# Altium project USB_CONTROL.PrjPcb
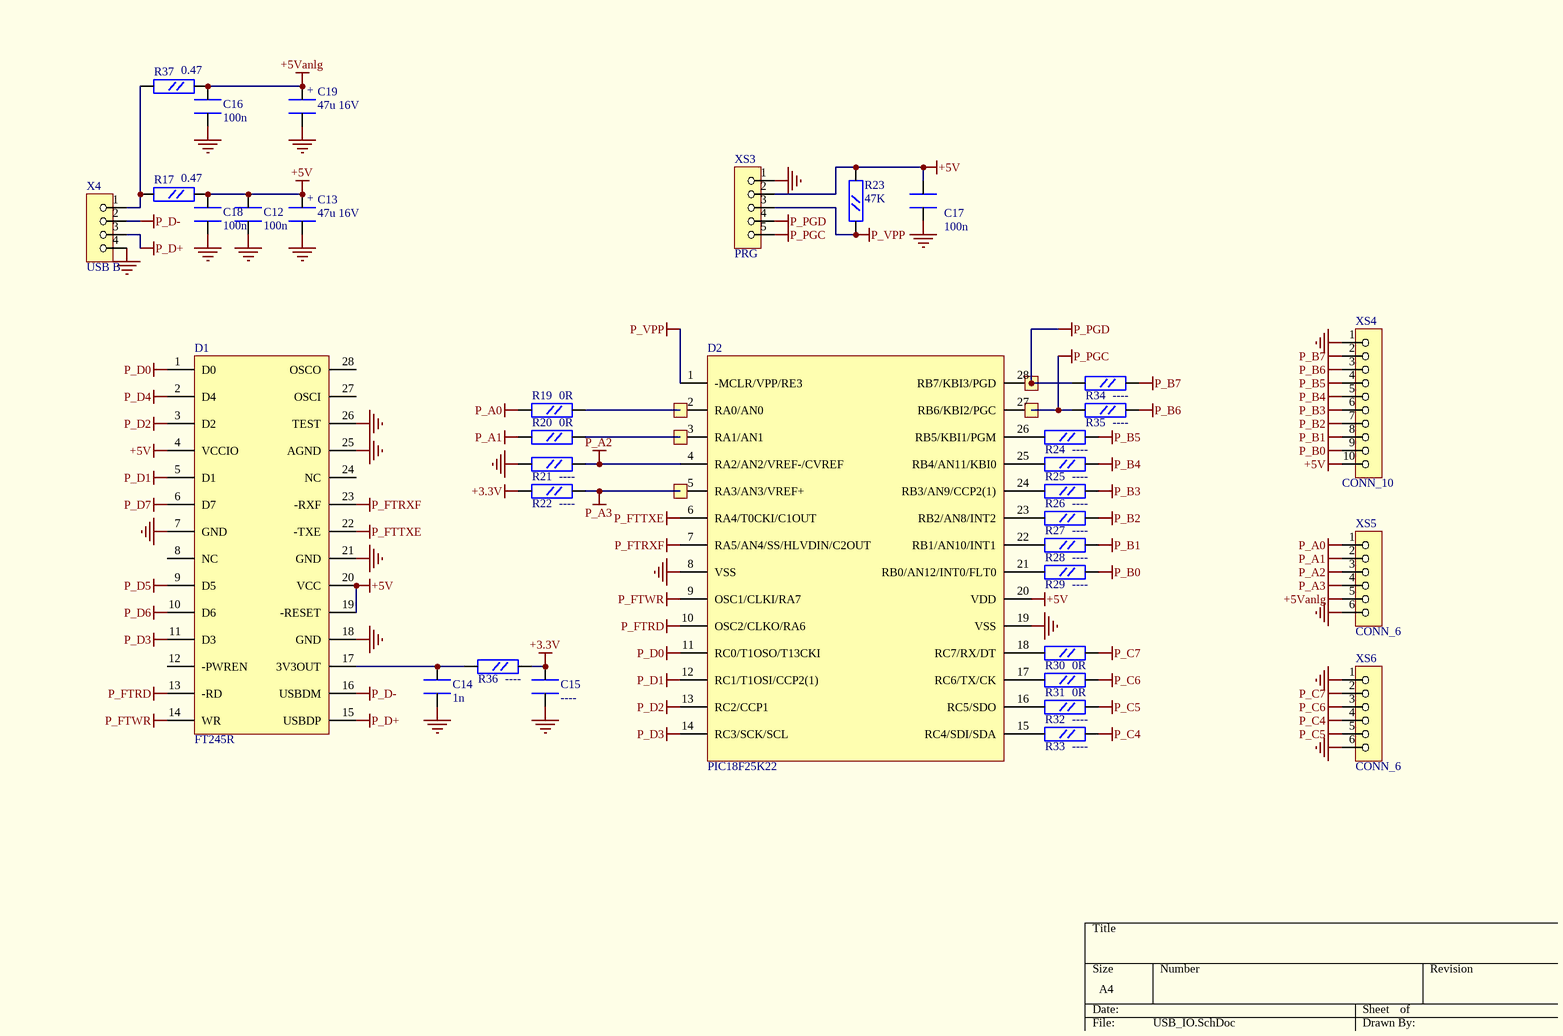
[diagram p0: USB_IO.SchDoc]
1 sheet, 35 parts. Net scope: global (net labels, ports and power ports of the same name join across sheets).
Board file: USB_IO.PcbDoc

## Sheet USB_IO.SchDoc
size A4; SheetNumber: 1; SheetTotal: 1; PageSetup: Record=PageOptions¦CenterHorizontal=True¦CenterVertical=True¦PrintScale=0.97¦XCorrection=1.00¦YCorrection=1.00¦PrintKind=2¦BorderSize=5000000¦LeftOffset=0¦BottomOffset=0¦Orientation=2¦PaperLength=1000¦PaperWidth=1000¦Scale=100¦PaperSource=7¦PrintQuality=-4¦MediaType=1¦DitherType=10¦PaperKind=A4¦PrintScaleMode=1

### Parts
C12  100n  [0603]
C13  47u 16V  [FC_B]
C14  1n  [0603]
C15  ----  [0603]
C16  100n  [0603]
C17  100n  [0603]
C18  100n  [0603]
C19  47u 16V  [FC_B]
D1  FT245R  [SSOP-28]
D2  PIC18F25K22  [SOL-28]
R17  0.47  [1206]
R19  0R  [0603]
R20  0R  [0603]
R21  ----  [0603]
R22  ----  [0603]
R23  47K  [0603]
R24  ----  [0603]
R25  ----  [0603]
R26  ----  [0603]
R27  ----  [0603]
R28  ----  [0603]
R29  ----  [0603]
R30  0R  [0603]
R31  0R  [0603]
R32  ----  [0603]
R33  ----  [0603]
R34  ----  [0603]
R35  ----  [0603]
R36  ----  [0603]
R37  0.47  [1206]
X4  USB B  [F_USB_B]
XS3  PRG  [SIP5]
XS4  CONN_10  [SIP-10]
XS5  CONN_6  [SIP-6]
XS6  CONN_6  [SIP-6]

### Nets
+3.3V: C15.1 R22.2 R36.1
+5V: C12.1 C13.1 C17.2 C18.1 D1.4(VCCIO) D1.19(-RESET) D1.20(VCC) D2.20(VDD) R17.1 R23.2 XS3.2 XS4.10
+5Vanlg: C16.1 C19.1 R37.1 XS5.5
GND: C12.2 C13.2 C14.1 C15.2 C16.2 C17.1 C18.2 C19.2 D1.7(GND) D1.18(GND) D1.21(GND) D1.25(AGND) D1.26(TEST) D2.8(VSS) D2.19(VSS) R21.2 X4.4 XS3.1 XS4.1 XS5.6 XS6.1 XS6.6
P_A0: R19.2 XS5.1
P_A1: R20.2 XS5.2
P_A2: D2.4(RA2/AN2/VREF-/CVREF) R21.1 XS5.3
P_A3: D2.5(RA3/AN3/VREF+) R22.1 XS5.4
P_B0: R29.1 XS4.9
P_B1: R28.1 XS4.8
P_B2: R27.1 XS4.7
P_B3: R26.1 XS4.6
P_B4: R25.1 XS4.5
P_B5: R24.1 XS4.4
P_B6: R35.1 XS4.3
P_B7: R34.1 XS4.2
P_C4: R33.1 XS6.4
P_C5: R32.1 XS6.5
P_C6: R31.1 XS6.3
P_C7: R30.1 XS6.2
P_D0: D1.1(D0) D2.11(RC0/T1OSO/T13CKI)
P_D1: D1.5(D1) D2.12(RC1/T1OSI/CCP2(1))
P_D2: D1.3(D2) D2.13(RC2/CCP1)
P_D3: D1.11(D3) D2.14(RC3/SCK/SCL)
P_D4: D1.2(D4)
P_D5: D1.9(D5)
P_D6: D1.10(D6)
P_D7: D1.6(D7)
P_D+: D1.15(USBDP) X4.3
P_D-: D1.16(USBDM) X4.2
P_FTRD: D1.13(-RD) D2.10(OSC2/CLKO/RA6)
P_FTRXF: D1.23(-RXF) D2.7(RA5/AN4/SS/HLVDIN/C2OUT)
P_FTTXE: D1.22(-TXE) D2.6(RA4/T0CKI/C1OUT)
P_FTWR: D1.14(WR) D2.9(OSC1/CLKI/RA7)
P_PGC: D2.27(RB6/KBI2/PGC) R35.2 XS3.5
P_PGD: D2.28(RB7/KBI3/PGD) R34.2 XS3.4
P_VPP: D2.1(-MCLR/VPP/RE3) R23.1 XS3.3
NetC14_2: C14.2 D1.17(3V3OUT) R36.2
NetD2_2: D2.2(RA0/AN0) R19.1
NetD2_3: D2.3(RA1/AN1) R20.1
NetD2_15: D2.15(RC4/SDI/SDA) R33.2
NetD2_16: D2.16(RC5/SDO) R32.2
NetD2_17: D2.17(RC6/TX/CK) R31.2
NetD2_18: D2.18(RC7/RX/DT) R30.2
NetD2_21: D2.21(RB0/AN12/INT0/FLT0) R29.2
NetD2_22: D2.22(RB1/AN10/INT1) R28.2
NetD2_23: D2.23(RB2/AN8/INT2) R27.2
NetD2_24: D2.24(RB3/AN9/CCP2(1)) R26.2
NetD2_25: D2.25(RB4/AN11/KBI0) R25.2
NetD2_26: D2.26(RB5/KBI1/PGM) R24.2
NetR17_2: R17.2 R37.2 X4.1

Not connected (* = marked no-connect by the designer): D1 8(NC) 12(-PWREN) 24(NC) 27(OSCI) 28(OSCO)

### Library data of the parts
C12 C14-C18 = C
C13 C19 = C_E
D2 = PIC18F2321
R17 R19-R37 = R_125
X4 = CONN_4: ТЕЛЕВИЗИОННЫЙ РАЗЪЕМ
XS3 = CONN_5: ТЕЛЕВИЗИОННЫЙ РАЗЪЕМ
XS4 = CONN_10: ТЕЛЕВИЗИОННЫЙ РАЗЪЕМ
XS5 XS6 = CONN_6: ТЕЛЕВИЗИОННЫЙ РАЗЪЕМ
